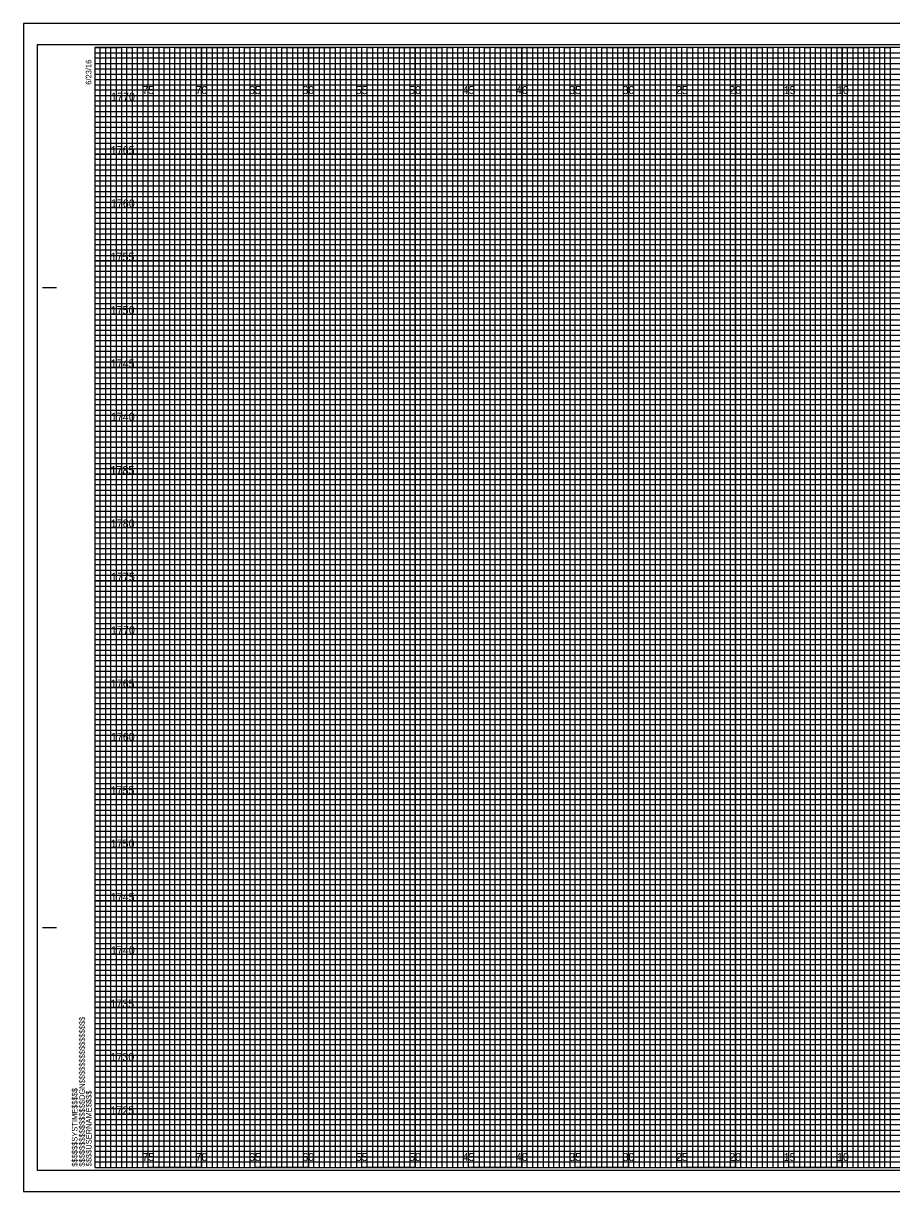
# Model space of a CAD drawing. Extents: x -7 to 162, y -2 to 217.
# Drawn here: x -6.7 to 74.6, y -2.3 to 107.3 of the extents above; entities that cross this region are included whole.
import ezdxf

# ---------------------------------------------------------------- set-up
doc = ezdxf.new("R2010")
doc.units = 0
for name, color, linetype in [('Prop XS Elevation Labels', 7, 'Continuous'), ('Prop XS Offset Labels', 7, 'Continuous'), ('Sheet Cross Section CELL', 7, 'Continuous'), ('Sheet Cross Section Grid Major CELL', 7, 'Continuous'), ('Sheet Cross Section Grid Middle CELL', 7, 'Continuous'), ('Sheet Cross Section Grid Minor 1 CELL', 7, 'Continuous'), ('Sheet Cross Section Grid Minor 2 CELL', 7, 'Continuous'), ('Sheet Cutting Line CELL', 7, 'Continuous'), ('Sheet DOT Grid CELL', 7, 'Continuous'), ('Sheet Plot Border Inside CELL', 7, 'Continuous'), ('Sheet Plot Border Outside CELL', 7, 'Continuous')]:
    doc.layers.add(name, color=color, linetype=linetype)

msp = doc.modelspace()

# ---------------------------------------------------------------- linework, layer by layer
at = {"layer": 'Sheet Cross Section CELL'}
for p, q in [((-4.9, 82.5), (-3.65, 82.5)), ((-4.85, 82.5), (-3.6, 82.5)), ((-4.9, 22.5), (-3.65, 22.5)), ((-4.85, 22.5), (-3.6, 22.5)), ((0, 0), (0, 0)), ((0, 0), (0, 0)), ((0, 0), (0, 0)), ((0, 0), (0, 0)), ((0, 0), (0, 0)), ((0, 0), (0, 0)), ((0, 0), (0, 0))]:
    msp.add_line(p, q, dxfattribs=at)
msp.add_lwpolyline([(160, 105), (0, 105), (0, 0), (160, 0)], close=True, dxfattribs=at)
at = {"layer": 'Sheet Cross Section Grid Major CELL'}
for p, q in [((5, 105), (0, 105)), ((5, 0), (5, 105)), ((15, 105), (10, 105)), ((10, 105), (10, 0)), ((15, 0), (15, 105)), ((25, 105), (20, 105)), ((20, 105), (20, 0)), ((25, 0), (25, 105)), ((35, 105), (30, 105)), ((30, 105), (30, 0)), ((35, 0), (35, 105)), ((45, 105), (40, 105)), ((40, 105), (40, 0)), ((45, 0), (45, 105)), ((55, 105), (50, 105)), ((50, 105), (50, 0)), ((55, 0), (55, 105)), ((65, 105), (60, 105)), ((60, 105), (60, 0)), ((65, 0), (65, 105)), ((75, 105), (70, 105)), ((70, 105), (70, 0)), ((10, 0), (5, 0)), ((20, 0), (15, 0)), ((30, 0), (25, 0)), ((40, 0), (35, 0)), ((50, 0), (45, 0)), ((60, 0), (55, 0)), ((70, 0), (65, 0))]:
    msp.add_line(p, q, dxfattribs=at)
for points in [[(0, 100), (160, 100), (160, 95), (0, 95)], [(0, 90), (160, 90), (160, 85), (0, 85)], [(0, 80), (160, 80), (160, 75), (0, 75)], [(0, 70), (160, 70), (160, 65), (0, 65)], [(0, 60), (160, 60), (160, 55), (0, 55)], [(0, 50), (160, 50), (160, 45), (0, 45)], [(0, 40), (160, 40), (160, 35), (0, 35)], [(0, 30), (160, 30), (160, 25), (0, 25)], [(0, 20), (160, 20), (160, 15), (0, 15)], [(0, 10), (160, 10), (160, 5), (0, 5)]]:
    msp.add_lwpolyline(points, dxfattribs=at)
at = {"layer": 'Sheet Cross Section Grid Middle CELL'}
for points in [[(0, 105), (2.5, 105), (2.5, 0), (7.5, 0), (7.5, 105), (12.5, 105), (12.5, 0), (17.5, 0), (17.5, 105), (22.5, 105), (22.5, 0), (27.5, 0), (27.5, 105), (32.5, 105), (32.5, 0), (37.5, 0), (37.5, 105), (42.5, 105), (42.5, 0), (47.5, 0), (47.5, 105), (52.5, 105), (52.5, 0), (57.5, 0), (57.5, 105), (62.5, 105), (62.5, 0), (67.5, 0), (67.5, 105), (72.5, 105), (72.5, 0), (77.5, 0)], [(0, 102.5), (137.5, 102.5)], [(0, 92.5), (160, 92.5), (160, 97.5), (0, 97.5)], [(0, 82.5), (160, 82.5), (160, 87.5), (0, 87.5)], [(0, 72.5), (160, 72.5), (160, 77.5), (0, 77.5)], [(0, 62.5), (160, 62.5), (160, 67.5), (0, 67.5)], [(0, 52.5), (160, 52.5), (160, 57.5), (0, 57.5)], [(0, 42.5), (160, 42.5), (160, 47.5), (0, 47.5)], [(0, 32.5), (160, 32.5), (160, 37.5), (0, 37.5)], [(0, 22.5), (160, 22.5), (160, 27.5), (0, 27.5)], [(0, 12.5), (160, 12.5), (160, 17.5), (0, 17.5)], [(0, 2.5), (160, 2.5), (160, 7.5), (0, 7.5)]]:
    msp.add_lwpolyline(points, dxfattribs=at)
at = {"layer": 'Sheet Cross Section Grid Minor 1 CELL'}
for p, q in [((0, 104.5), (130, 104.5)), ((130, 103.99), (0, 103.99)), ((0, 103.99), (0, 103.5)), ((0, 103.5), (130, 103.5)), ((130, 102.95), (0, 102.95)), ((0, 102.95), (0, 102)), ((0, 102), (160, 102))]:
    msp.add_line(p, q, dxfattribs=at)
for points in [[(0, 101.5), (135, 101.5), (160, 101.5), (160, 101), (0, 101)], [(0, 100.5), (160, 100.5), (160, 99.5), (0, 99.5)], [(0, 99), (160, 99), (160, 98.5), (0, 98.49)], [(0, 98), (160, 98), (160, 97), (0, 97)], [(0, 96.5), (160, 96.5), (160, 96), (0, 96)], [(0, 95.5), (160, 95.5), (160, 94.5), (0, 94.5)], [(0, 94), (160, 94), (160, 93.5), (0, 93.5)], [(0, 93), (160, 93), (160, 92), (0, 92)], [(0, 91.5), (160, 91.5), (160, 91), (0, 91)], [(0, 90.5), (160, 90.5), (160, 89.5), (0, 89.5)], [(0, 89), (160, 89), (160, 88.5), (0, 88.5)], [(0, 88), (160, 88), (160, 86.98), (160, 86.5), (160, 86), (0, 86)], [(0, 87), (160, 87), (160, 86.5), (0, 86.5)], [(0, 85.5), (160, 85.5), (160, 84.5), (0, 84.52)], [(0, 84.52), (160, 84.5), (160, 84), (0, 84)], [(0, 83.5), (160, 83.5), (160, 83), (0, 83)], [(0, 82), (160, 82), (160, 81.5), (0, 81.5)], [(0, 81), (160, 81), (160, 80.5), (0, 80.5)], [(-0.04, 79.45), (160, 79.45), (160, 78.94), (-0.04, 78.94)], [(0, 78.5), (160, 78.5), (160, 78), (0, 78)], [(0, 77), (160, 77), (160, 76.5), (0, 76.5)], [(0, 76), (160, 76), (160, 75.5), (0, 75.5)], [(0, 74.5), (160, 74.5), (160, 74), (0, 74)], [(0, 73.5), (160, 73.5), (160, 73), (0, 73)], [(0, 72), (160, 72), (160, 71.5), (0, 71.5)], [(0, 71), (160, 71), (160, 70.5), (0, 70.5)], [(0, 69.5), (160, 69.5), (160, 68.99), (0, 69)], [(0, 68.5), (160, 68.5), (160, 68), (0, 68)], [(0, 67), (160, 67), (160, 66.5), (0, 66.5)], [(0, 66), (160, 66), (160, 65.5), (0, 65.5)], [(0, 64.5), (160, 64.5), (160, 64), (0, 64)], [(0, 63.5), (160, 63.5), (160, 63), (0, 63)], [(0, 62), (160, 62), (160, 61.5), (0, 61.5)], [(0, 61), (160, 61), (160, 60.5), (0, 60.5)], [(0, 59.5), (160, 59.5), (160, 59), (0, 59)], [(0, 58.5), (160.03, 58.45), (160, 58), (0, 58)], [(0, 57), (160, 57), (160, 56.5), (0, 56.5)], [(0, 56), (160, 56), (160, 55.5), (0, 55.5)], [(0, 54.5), (160, 54.5), (160, 54), (0, 54)], [(0, 53.5), (160, 53.5), (160, 53), (0, 53)], [(0, 52), (160, 52), (160, 51.5), (0, 51.5)], [(0, 51), (160, 51), (160, 50.5), (0, 50.5)], [(0, 49.5), (160, 49.5), (160, 49), (0, 49)], [(0, 48.5), (160, 48.5), (160, 48), (0, 48)], [(0, 47), (160, 47), (160, 46.5), (0, 46.5)], [(0, 46), (160, 46), (160, 45.5), (0, 45.5)], [(0, 44.5), (160, 44.5), (160, 44), (0, 44)], [(0, 43.5), (160, 43.5), (160, 43), (0, 43)], [(0, 42), (160, 42), (160, 41.5), (0, 41.5)], [(0, 41), (160, 41), (160, 40.5), (0, 40.5)], [(0, 39.5), (160, 39.5), (160, 38.99), (0, 39)], [(0, 38.5), (160, 38.5), (160, 38), (0, 38)], [(0, 37), (160, 37), (160, 36.5), (0, 36.5)], [(0, 36), (160, 36), (160, 35.5), (0, 35.5)], [(0, 34.5), (160, 34.5), (160, 34), (0, 34)], [(0, 33.5), (160, 33.5), (160, 33), (0, 33)], [(0, 32), (160, 32), (160, 31.5), (0, 31.5)], [(0, 31), (160, 31), (160, 30.5), (0, 30.5)], [(0, 29.5), (160, 29.5), (160, 29), (0, 29)], [(0, 28.5), (160.03, 28.46), (160, 28), (0, 28)], [(0, 27), (160, 27), (160, 26.5), (0, 26.5)], [(0, 26), (160, 26), (160, 25.5), (0, 25.5)], [(0, 24.5), (160, 24.5), (160, 24), (0, 24)], [(0, 23.5), (160, 23.5), (160, 23), (0, 23)], [(0, 22), (160, 22), (160, 21.5), (0, 21.5)], [(0, 21), (160, 21), (160, 20.5), (0, 20.5)], [(0, 19.5), (160, 19.5), (160, 19), (0, 19)], [(0, 18.5), (160, 18.5), (160, 18), (0, 18)], [(0, 17), (160, 17), (160, 16.5), (0, 16.5)], [(0, 16), (160, 16), (160, 15.5), (0, 15.5)], [(0, 14.5), (160, 14.5), (160, 14), (0, 14)], [(0, 13.5), (160, 13.5), (160, 13), (0, 13)], [(0, 12), (160, 12), (160, 11.5), (0, 11.5)], [(0, 11), (160, 11), (160, 10.5), (0, 10.5)], [(0, 9.5), (160, 9.5), (160, 9), (0, 9)], [(0, 8.5), (160, 8.5), (160, 8), (0, 8)], [(0, 7), (160, 7), (160, 6.5), (0, 6.5)], [(0, 6), (160, 6), (160, 5.5), (0, 5.5)], [(0, 4.5), (160, 4.5), (160, 4), (0, 4)], [(0, 3.5), (160, 3.5), (160, 3), (0, 3)], [(0, 2), (160, 2), (160, 1.5), (0, 1.5)], [(0, 1), (160, 1), (160, 0.5), (0, 0.5)]]:
    msp.add_lwpolyline(points, dxfattribs=at)
at = {"layer": 'Sheet Cross Section Grid Minor 2 CELL'}
for points in [[(0, 0), (0.5, 0), (0.5, 105), (1, 105), (1, 0)], [(1, 0), (1.5, 0), (1.5, 105), (2, 105), (2, 0)], [(2.5, 0), (3, 0), (3, 105), (3.5, 105), (3.5, 0)], [(3.5, 0), (4, 0), (4, 105), (4.5, 105), (4.5, 0)], [(5, 0), (5.5, 0), (5.5, 105), (6, 105), (6, 0)], [(6, 0), (6.5, 0), (6.5, 105), (7, 105), (7, 0)], [(7.5, 0), (8, 0), (8, 105), (8.5, 105), (8.5, 0)], [(8.5, 0), (9, 0), (9, 105), (9.5, 105), (9.5, 0)], [(10, 0), (10.5, 0), (10.5, 105), (11, 105), (11, 0)], [(11, 0), (11.5, 0), (11.5, 105), (12, 105), (12, 0)], [(12.5, 0), (13, 0), (13, 105), (13.5, 105), (13.5, 0)], [(13.5, 0), (14, 0), (14, 105), (14.5, 105), (14.5, 0)], [(15, 0), (15.5, 0), (15.5, 105), (16, 105), (16, 0)], [(16, 0), (16.5, 0), (16.5, 105), (17, 105), (17, 0)], [(17.5, 0), (18, 0), (18, 105), (18.5, 105), (18.5, 0)], [(18.5, 0), (19, 0), (19, 105), (19.5, 105), (19.5, 0)], [(20, 0), (20.5, 0), (20.5, 105), (21, 105), (21, 0)], [(21, 0), (21.5, 0), (21.5, 105), (22, 105), (22, 0)], [(22.5, 0), (23, 0), (23, 105), (23.5, 105), (23.5, 0)], [(23.5, 0), (24, 0), (24, 105), (24.5, 105), (24.5, 0)], [(25, 0), (25.5, 0), (25.5, 105), (26, 105), (26, 0)], [(26, 0), (26.5, 0), (26.5, 105), (27, 105), (27, 0)], [(27.5, 0), (28, 0), (28, 105), (28.5, 105), (28.5, 0)], [(28.5, 0), (29, 0), (29, 105), (29.5, 105), (29.5, 0)], [(30, 0), (30.5, 0), (30.5, 105), (31, 105), (31, 0)], [(31, 0), (31.5, 0), (31.5, 105), (32, 105), (32, 0)], [(32.5, 0), (33, 0), (33, 105), (33.5, 105), (33.5, 0)], [(33.5, 0), (34, 0), (34, 105), (34.5, 105), (34.5, 0)], [(35, 0), (35.5, 0), (35.5, 105), (36, 105), (36, 0)], [(36, 0), (36.5, 0), (36.5, 105), (37, 105), (37, 0)], [(37.5, 0), (38, 0), (38, 105), (38.5, 105), (38.5, 0)], [(38.5, 0), (39, 0), (39, 105), (39.5, 105), (39.5, 0)], [(40, 0), (40.5, 0), (40.5, 105), (41, 105), (41, 0)], [(41, 0), (41.5, 0), (41.5, 105), (42, 105), (42, 0)], [(42.5, 0), (43, 0), (43, 105), (43.5, 105), (43.5, 0)], [(43.5, 0), (44, 0), (44, 105), (44.5, 105), (44.5, 0)], [(45, 0), (45.5, 0), (45.5, 105), (46, 105), (46, 0)], [(46, 0), (46.5, 0), (46.5, 105), (47, 105), (47, 0)], [(47.5, 0), (48, 0), (48, 105), (48.5, 105), (48.5, 0)], [(48.5, 0), (49, 0), (49, 105), (49.5, 105), (49.5, 0)], [(50, 0), (50.5, 0), (50.5, 105), (51, 105), (51, 0)], [(51, 0), (51.5, 0), (51.5, 105), (52, 105), (52, 0)], [(52.5, 0), (53, 0), (53, 105), (53.5, 105), (53.5, 0)], [(53.5, 0), (54, 0), (54, 105), (54.5, 105), (54.5, 0)], [(55, 0), (55.5, 0), (55.5, 105), (56, 105), (56, 0)], [(56, 0), (56.5, 0), (56.5, 105), (57, 105), (57, 0)], [(57.5, 0), (58, 0), (58, 105), (58.5, 105), (58.5, 0)], [(58.5, 0), (59, 0), (59, 105), (59.5, 105), (59.5, 0)], [(60, 0), (60.5, 0), (60.5, 105), (61, 105), (61, 0)], [(61, 0), (61.5, 0), (61.5, 105), (62, 105), (62, 0)], [(62.5, 0), (63, 0), (63, 105), (63.5, 105), (63.5, 0)], [(63.5, 0), (64, 0), (64, 105), (64.5, 105), (64.5, 0)], [(65, 0), (65.5, 0), (65.5, 105), (66, 105), (66, 0)], [(66, 0), (66.5, 0), (66.5, 105), (67, 105), (67, 0)], [(67.5, 0), (68, 0), (68, 105), (68.5, 105), (68.5, 0)], [(68.5, 0), (69, 0), (69, 105), (69.5, 105), (69.5, 0)], [(70, 0), (70.5, 0), (70.5, 105), (71, 105), (71, 0)], [(71, 0), (71.5, 0), (71.5, 105), (72, 105), (72, 0)], [(72.5, 0), (73, 0), (73, 105), (73.5, 105), (73.5, 0)], [(73.5, 0), (74, 0), (74, 105), (74.5, 105), (74.5, 0)]]:
    msp.add_lwpolyline(points, dxfattribs=at)
at = {"layer": 'Sheet Cutting Line CELL'}
for p, q in [((161.65, 107.25), (-6.7, 107.25)), ((-6.7, 107.25), (-6.7, -2.25)), ((-6.7, -2.25), (161.65, -2.25))]:
    msp.add_line(p, q, dxfattribs=at)
at = {"layer": 'Sheet DOT Grid CELL'}
for p, q in [((5, 0), (5, 105)), ((10, 0), (10, 105)), ((15, 0), (15, 105)), ((20, 0), (20, 105)), ((25, 0), (25, 105)), ((30, 0), (30, 105)), ((35, 0), (35, 105)), ((40, 0), (40, 105)), ((45, 0), (45, 105)), ((50, 0), (50, 105)), ((55, 0), (55, 105)), ((60, 0), (60, 105)), ((65, 0), (65, 105)), ((70, 0), (70, 105)), ((0, 100), (160, 100)), ((0, 95), (160, 95)), ((0, 90), (160, 90)), ((0, 85), (160, 85)), ((0, 80), (160, 80)), ((0, 75), (160, 75)), ((0, 70), (160, 70)), ((0, 65), (160, 65)), ((0, 60), (160, 60)), ((0, 55), (160, 55)), ((0, 50), (160, 50)), ((0, 45), (160, 45)), ((0, 40), (160, 40)), ((0, 35), (160, 35)), ((0, 30), (160, 30)), ((0, 25), (160, 25)), ((0, 20), (160, 20)), ((0, 15), (160, 15)), ((0, 10), (160, 10)), ((0, 5), (160, 5))]:
    msp.add_line(p, q, dxfattribs=at)
at = {"layer": 'Sheet Plot Border Inside CELL'}
msp.add_lwpolyline([(-5.4, -0.25), (161.2, -0.25), (161.2, 105.25), (-5.4, 105.25)], close=True, dxfattribs=at)
at = {"layer": 'Sheet Plot Border Outside CELL'}
msp.add_lwpolyline([(-6.7, -2.25), (161.65, -2.25), (161.65, 107.25), (-6.7, 107.25)], close=True, dxfattribs=at)

# ---------------------------------------------------------------- texts
at = {"layer": 'Prop XS Elevation Labels'}
for s, p in [('1770', (1.52, 100)), ('1765', (1.49, 95)), ('1760', (1.5, 90)), ('1755', (1.47, 85)), ('1750', (1.48, 80)), ('1745', (1.49, 75)), ('1740', (1.5, 70)), ('1735', (1.45, 65)), ('1785', (1.48, 65)), ('1780', (1.49, 60)), ('1775', (1.51, 55)), ('1770', (1.52, 50)), ('1765', (1.49, 45)), ('1760', (1.5, 40)), ('1755', (1.47, 35)), ('1750', (1.48, 30)), ('1745', (1.49, 25)), ('1740', (1.5, 20)), ('1735', (1.45, 15)), ('1730', (1.46, 10)), ('1725', (1.46, 5))]:
    msp.add_text(s, height=0.75, dxfattribs=at).set_placement(p)
at = {"layer": 'Prop XS Offset Labels'}
for s, p in [('75', (4.44, 100.62)), ('70', (9.43, 100.62)), ('65', (14.44, 100.62)), ('60', (19.43, 100.62)), ('55', (24.44, 100.62)), ('50', (29.43, 100.62)), ('45', (34.44, 100.62)), ('40', (39.43, 100.62)), ('35', (44.44, 100.62)), ('30', (49.43, 100.62)), ('25', (54.44, 100.62)), ('20', (59.43, 100.62)), ('15', (64.53, 100.62)), ('10', (69.52, 100.62)), ('75', (4.44, 0.62)), ('70', (9.43, 0.62)), ('65', (14.44, 0.62)), ('60', (19.43, 0.62)), ('55', (24.44, 0.62)), ('50', (29.43, 0.62)), ('45', (34.44, 0.62)), ('40', (39.43, 0.62)), ('35', (44.44, 0.62)), ('30', (49.43, 0.62)), ('25', (54.44, 0.62)), ('20', (59.43, 0.62)), ('15', (64.53, 0.62)), ('10', (69.52, 0.62))]:
    msp.add_text(s, height=0.75, dxfattribs=at).set_placement(p)
at = {"layer": 'Sheet Cross Section CELL'}
for s, p in [('6/23/16', (-0.33, 101.5)), ('$$$$$$$$$$$$$$$$DGN$$$$$$$$$$$$$$$$', (-0.94, 0.09)), ('$$$$$$SYSTIME$$$$$', (-1.63, 0.09)), ('$$$$USERNAME$$$$', (-0.31, 0.12))]:
    msp.add_text(s, height=0.525, rotation=90, dxfattribs=at).set_placement(p)

doc.saveas('drawing.dxf')
